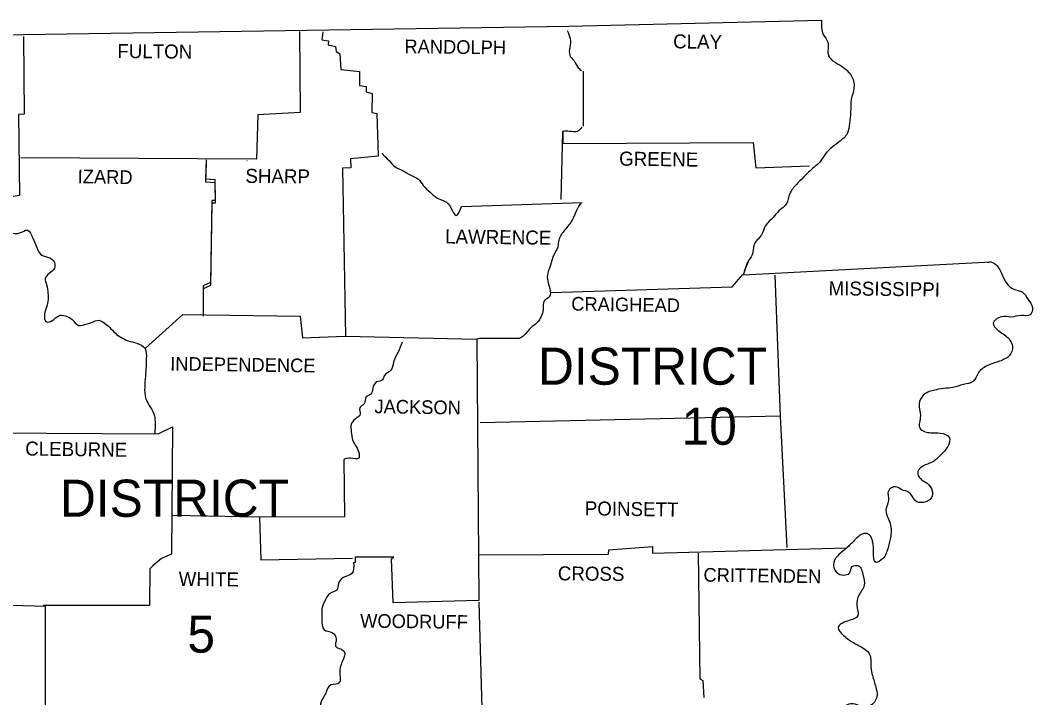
# Model space of a CAD drawing. Extents: x -33639 to 34530, y -17264 to 5867.
# Drawn here: x 2998 to 4708, y -8278 to -7133 of the extents above; entities that cross this region are included whole.
import ezdxf

# ---------------------------------------------------------------- set-up
doc = ezdxf.new("R2010")
doc.units = 0
for name, color, linetype in [('1', 7, 'Continuous'), ('2', 7, 'Continuous'), ('3', 7, 'Continuous')]:
    doc.layers.add(name, color=color, linetype=linetype)

msp = doc.modelspace()

# ---------------------------------------------------------------- linework, layer by layer
at = {"layer": '1'}
for p, q in [((4219.3, -7563.1), (4225.9, -7542.7)), ((4221, -7556.5), (4227.6, -7540.5)), ((3563.3, -8039.7), (3628.8, -8039.7)), ((3563.3, -8039.7), (3563.3, -8049)), ((3624.9, -8043), (3628.8, -8039.7))]:
    msp.add_line(p, q, dxfattribs=at)
for points in [[(1332.2, -7158.5), (2222.1, -7159.1), (3003, -7157.4), (3924.3, -7143.1), (4351.4, -7133.2)], [(3003, -7160.7), (3004.1, -7291.7), (2994.8, -7292.3), (2996.4, -7429.3), (2957.9, -7434.8), (2961.2, -7471.7), (2974.4, -7488.8), (2973.3, -7532.2), (2898.5, -7535), (2895.7, -7602.1), (2827.5, -7604.3), (2824.2, -7685.8), (2828, -7692.4), (2829.7, -7822.3), (2947.5, -7830), (2945.8, -8120), (3039.4, -8122.8), (3039.4, -8417.8), (2965.6, -8423.3), (2960.1, -8488.2), (2836.3, -8488.8)], [(3469.2, -7152.5), (3470.3, -7289), (3398.7, -7292.8), (3396.5, -7367.7), (2998.6, -7365.5)], [(3508.8, -7153), (3507.2, -7166.3), (3518.2, -7167.9), (3517.6, -7174.5), (3530.3, -7177.3), (3531.4, -7186.1), (3537.4, -7189.9), (3539.1, -7216.3), (3570.5, -7219.6), (3570.5, -7243.3), (3582, -7245), (3582, -7254.3), (3591.9, -7257.1), (3591.4, -7289), (3600.2, -7290.6), (3602.4, -7362.7), (3555.6, -7367.1), (3556.1, -7382.5), (3541.8, -7383.1), (3546.8, -7667.1), (3768.6, -7672), (3772.4, -8113.4), (3627.7, -8117.3), (3624.9, -8043)], [(3948.5, -7219.1), (3948.5, -7312.1)], [(3911.1, -7435.9), (3913.9, -7320.9), (3913.9, -7341.3), (4235.8, -7339.6), (4240.2, -7382.5), (4331, -7379.2)], [(3311.8, -7369.3), (3310.7, -7401.3), (3326.1, -7402.4), (3326.6, -7437.6), (3321.1, -7437.6), (3318.9, -7576.3), (3306.3, -7581.8), (3306.3, -7628)], [(3380.6, -7370.4), (3381.1, -7369.9)], [(3311.8, -7374.3), (3310.7, -7406.2), (3326.1, -7407.3), (3326.6, -7442.5), (3321.1, -7442.5), (3318.9, -7581.2), (3306.3, -7586.7), (3306.3, -7633)], [(3742.7, -7448), (3946.9, -7440.9)], [(4219.3, -7563.1), (4637, -7541.6)], [(3894.6, -7593.3), (4200.1, -7583.4), (4218.2, -7562.5)], [(4272.2, -7563.6), (4281.5, -7801.9), (4292.5, -8023.7)], [(3209.4, -7686.9), (3272.2, -7630.2), (3470.3, -7633), (3474.1, -7669.8), (3546.2, -7667.1)], [(3840.7, -7670.9), (3773.5, -7670.9), (3768.6, -7672)], [(4281.5, -7801.9), (3774.6, -7813.5)], [(2947.5, -7830), (3230.3, -7831.6), (3254.6, -7820.1), (3252.9, -8035.3), (3236.4, -8042.4), (3221.5, -8055.1), (3216.6, -8060), (3216, -8121.7), (3036.1, -8121.7)], [(3544, -7875.1), (3545.1, -7972), (3402, -7972.5), (3255.1, -7969.8)], [(3402, -7972.5), (3404.2, -8044.6), (3558.9, -8041.9)], [(3771.8, -8036.4), (3991.5, -8035.3), (3992, -8027.6), (4065.8, -8022.1), (4065.8, -8033.6), (4393.5, -8024.6)], [(4142.8, -8033.6), (4145.6, -8245.5), (4150.5, -8248.8), (4152.2, -8277.4)], [(3563.3, -8049), (3560.5, -8049.6)], [(3772.5, -8116.2), (3780.7, -8415), (3649.7, -8415.6), (3649.2, -8427.7), (3611.2, -8429.9), (3607.9, -8492.6), (3561.6, -8492.6)]]:
    msp.add_lwpolyline(points, dxfattribs=at)
for points in [[(4351.4, -7133.2), (4354.2, -7157.4), (4361.9, -7170.1), (4363, -7193.2), (4372.3, -7203.1), (4388.3, -7213), (4402.6, -7229), (4405.9, -7247.7), (4401.5, -7267), (4400.4, -7288.4), (4398.2, -7307.1), (4394.9, -7324.2), (4381.7, -7338), (4369, -7347.9), (4357.5, -7359.4), (4349.2, -7371.5), (4334.9, -7384.7), (4320.6, -7398.5), (4309, -7410.6), (4297.5, -7426), (4292, -7443.1), (4279.3, -7455.2), (4269.4, -7466.2), (4256.2, -7481.1), (4249.6, -7495.9), (4236.9, -7513), (4234.2, -7529.5), (4225.9, -7542.7), (4225.4, -7544.9)], [(3921.6, -7150.3), (3926.5, -7164.1), (3926, -7178.9), (3926, -7192.7), (3933.1, -7202), (3940.3, -7213.6), (3945.8, -7218.5)], [(3946.3, -7313.7), (3939.2, -7320.9), (3925.4, -7320.9), (3913.9, -7320.9)], [(3608.4, -7357.8), (3620.5, -7370.4), (3631, -7380.9), (3643.1, -7386.9), (3657.4, -7395.2), (3670.1, -7401.8), (3678.3, -7412.3), (3689.9, -7423.8), (3701.4, -7433.2), (3719.6, -7442), (3725.7, -7451.3), (3733.9, -7462.9), (3742.7, -7448)], [(3945.2, -7441.4), (3937, -7454.6), (3930.4, -7470), (3917.2, -7487.7), (3907.3, -7504.7), (3905.6, -7516.3), (3897.9, -7531.7), (3893.5, -7547.1), (3888.6, -7560.3), (3888.6, -7574.1), (3892.4, -7587.8), (3891.3, -7600.5), (3883.1, -7606.5), (3880.9, -7622.5), (3877.6, -7633.5), (3870.4, -7644.5), (3859.9, -7652.8), (3848.9, -7665.4), (3840.7, -7670.9)], [(2974.4, -7488.8), (2996.4, -7492.6), (3009.6, -7487.7), (3019, -7502), (3024, -7513), (3032.2, -7528.9), (3045.4, -7533.9), (3055.3, -7542.7), (3055.3, -7552.1), (3046.5, -7560.9), (3039.9, -7569.7), (3042.1, -7580.1), (3044.3, -7594.4), (3044.3, -7608.2), (3041, -7620.8), (3038.3, -7632.4), (3041, -7642.3), (3051.5, -7640.7), (3062.5, -7632.4), (3074, -7632.4), (3085, -7638.5), (3096.6, -7648.9), (3108.2, -7646.7), (3117.5, -7644), (3130.7, -7640.1), (3140.1, -7645.1), (3148.3, -7651.7), (3158.2, -7662.1), (3167.6, -7668.7), (3179.7, -7674.8), (3194.6, -7678.6), (3208.3, -7688), (3210.5, -7703.9), (3210, -7717.7), (3208.9, -7734.8), (3207.8, -7753.5), (3209.4, -7771.6), (3215.5, -7783.8), (3223.2, -7798.1), (3225.4, -7811.3), (3224.8, -7832.2)], [(4631, -7542.1), (4637, -7541.6), (4655.8, -7561.4), (4664, -7577.9), (4676.1, -7587.3), (4689.9, -7592.2), (4700.3, -7604.9), (4707.5, -7618.6), (4703.6, -7630.8), (4688.2, -7631.9), (4671.2, -7634.6), (4654.7, -7634.1), (4641.4, -7645.1), (4653.5, -7659.9), (4669.5, -7673.7), (4673.9, -7688.5), (4665.1, -7702.8), (4647.5, -7710.6), (4630.4, -7717.2), (4615, -7730.4), (4607.9, -7743), (4590.8, -7748.5), (4573.2, -7753.5), (4557.8, -7755.1), (4540.2, -7758.4), (4523.1, -7766.7), (4516, -7781), (4518.2, -7801.4), (4517.6, -7822.8), (4535.8, -7830), (4551.7, -7830.5), (4567.1, -7838.8), (4565.5, -7850.9), (4553.9, -7866.3), (4540.2, -7878.4), (4526.4, -7884.5), (4513.8, -7896), (4518.2, -7907.6), (4529.7, -7915.3), (4538, -7927.9), (4536.9, -7939.5), (4523.7, -7947.8), (4509.4, -7944.5), (4498.9, -7930.7), (4486.8, -7926.3), (4476.3, -7921.3), (4464.2, -7928.5), (4464.2, -7944.5), (4459.8, -7961.5), (4463.7, -7974.2), (4468.6, -7991.8), (4468.1, -8005), (4463.7, -8023.7), (4454.3, -8043), (4443.3, -8049), (4438.9, -8028.1), (4436.7, -8011), (4430.1, -8001.1), (4421.3, -8000.6), (4409.7, -8008.8), (4397.1, -8021.5), (4381.1, -8035.3), (4371.8, -8049), (4376.7, -8066.1), (4388.8, -8070.5), (4398.2, -8067.2), (4403.1, -8056.2), (4412.5, -8054.5), (4421.3, -8071.6)], [(3642.5, -7677), (3635.9, -7694), (3628.2, -7710.6), (3623.3, -7724.9), (3612.8, -7733.1), (3609.5, -7740.8), (3600.2, -7744.1), (3593, -7755.1), (3589.7, -7765), (3582, -7769.4), (3578.2, -7781.5), (3571, -7788.2), (3571.6, -7799.2), (3563.3, -7806.9), (3556.7, -7815.7), (3556.7, -7827.8), (3559.4, -7843.7), (3564.9, -7853.1), (3569.9, -7865.2), (3569.4, -7872.9), (3555.6, -7872.9), (3544, -7875.1)], [(3560.5, -8049.6), (3557.8, -8067.7), (3547.3, -8072.7), (3535.2, -8084.8), (3532.5, -8095.8), (3522.6, -8100.2), (3513.2, -8111.8), (3507.2, -8127.7), (3507.2, -8144.2), (3511, -8162.9), (3524.8, -8167.9), (3531.4, -8178.9), (3530.3, -8190.5), (3543.5, -8198.2), (3545.7, -8204.8), (3543.5, -8211.9), (3537.4, -8232.3), (3538, -8246), (3536.9, -8252.1), (3522, -8256), (3513.2, -8270.8), (3507.2, -8281.3), (3505, -8295), (3506.6, -8304.9), (3502.2, -8312.6), (3500.6, -8324.2), (3495.1, -8334.1), (3490.1, -8343.5), (3495.6, -8354.5), (3494, -8362.2), (3490.7, -8374.3), (3493.4, -8378.1)], [(4421.3, -8071.6), (4423.5, -8087.5), (4414.1, -8104.6), (4410.8, -8121.7), (4412.5, -8138.7), (4394.9, -8148.1), (4379.5, -8159.1), (4388.3, -8172.3), (4404.8, -8184.4), (4421.3, -8193.8), (4431.8, -8203.1), (4434.5, -8225.7), (4437.3, -8240), (4442.8, -8259.8), (4445, -8273.6), (4435.1, -8290.1), (4423.5, -8293.4), (4411.4, -8289.5), (4397.1, -8288.4), (4385.5, -8299.4), (4377.3, -8314.8), (4369, -8330.3), (4363, -8343.5), (4356.9, -8357.8), (4344.8, -8374.3), (4329.9, -8377), (4312.3, -8381.4), (4301.9, -8393.5), (4303.5, -8413.9), (4313.4, -8427.7), (4321.1, -8444.7), (4326.6, -8459.6), (4323.9, -8478.3), (4316.2, -8492.1), (4306.3, -8500.3), (4301.9, -8517.9), (4294.7, -8531.1), (4288.1, -8535.5), (4274.9, -8534.4), (4260.6, -8531.7), (4248.5, -8532.8), (4236.9, -8538.8), (4225.4, -8535), (4213.3, -8521.8), (4203.4, -8511.9), (4192.4, -8508), (4180.8, -8514.1), (4178.6, -8532.2), (4184.1, -8550.9), (4189.1, -8576.3), (4184.1, -8591.7), (4182.4, -8617)]]:
    msp.add_spline(points, degree=3, dxfattribs=at)

# ---------------------------------------------------------------- texts
at = {"layer": '2'}
for s, height, rotation, p in [('RANDOLPH', 23.11, 359.2583, (3646.4, -7188.8)), ('CLAY', 23.66, 359.2258, (4100.4, -7180.6)), ('FULTON', 23.66, 359.4996, (3161.5, -7197.1)), ('GREENE', 23.67, 359.2361, (4009.1, -7378.7)), ('IZARD', 23.11, 358.9258, (3094.4, -7408.4)), ('SHARP', 23.66, 359.3905, (3377.8, -7407.9)), ('LAWRENCE', 23.67, 359.2678, (3715.2, -7510.2)), ('MISSISSIPPI', 23.66, 359.3097, (4363, -7597.7)), ('CRAIGHEAD', 23.11, 359.1159, (3928.2, -7623.6)), ('INDEPENDENCE', 23.108, 359.2187, (3250.7, -7724.9)), ('JACKSON', 23.11, 359.1352, (3595.8, -7797)), ('CLEBURNE', 23.66, 359.2535, (3005.8, -7868.5)), ('POINSETT', 23.66, 359.1987, (3951.1, -7969.5)), ('CROSS', 23.66, 359.3839, (3905.6, -8079.3)), ('WHITE', 23.67, 359.3139, (3265, -8088.6)), ('CRITTENDEN', 23.11, 359.213, (4151.6, -8081.5)), ('WOODRUFF', 23.11, 359.2748, (3571.6, -8159.1))]:
    msp.add_text(s, height=height, rotation=rotation, dxfattribs=at).set_placement(p)
at = {"layer": '3'}
for s, height, p in [('DISTRICT', 62.74, (3872.3, -7748.9)), ('10', 62.74, (4114.8, -7850.4)), ('DISTRICT', 62.74, (3064.7, -7972)), ('5', 62.7, (3279.9, -8201.5))]:
    msp.add_text(s, height=height, dxfattribs=at).set_placement(p)

doc.saveas('drawing.dxf')
